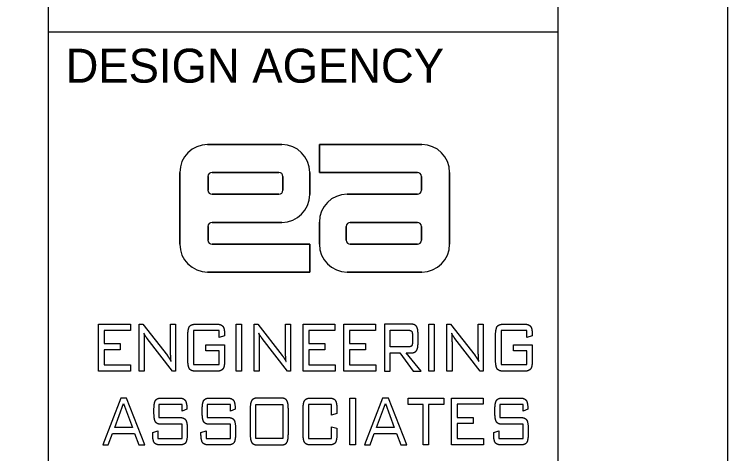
# Model space of a CAD drawing. Extents: x 0 to 34, y -1.9 to 22.
# Drawn here: x 31.899 to 34, y 3.757 to 5.052 of the extents above; entities that cross this region are included whole.
import ezdxf

# ---------------------------------------------------------------- set-up
doc = ezdxf.new("R2010")
doc.units = 0
for name, color, linetype in [('SH_Border', 7, 'Continuous'), ('SH_Cut_Line', 7, 'Continuous'), ('SH_Data', 7, 'Continuous'), ('TX_X_20', 7, 'Continuous')]:
    doc.layers.add(name, color=color, linetype=linetype)

msp = doc.modelspace()

# ---------------------------------------------------------------- linework, layer by layer
at = {"layer": 'SH_Border'}
for p, q in [((32, 0.5), (32, 21.5)), ((32, 5), (33.5, 5))]:
    msp.add_line(p, q, dxfattribs=at)
msp.add_lwpolyline([(1.5, 21.5), (33.5, 21.5), (33.5, 0.5), (1.5, 0.5)], close=True, dxfattribs=at)
at = {"layer": 'SH_Cut_Line'}
msp.add_lwpolyline([(0, 0), (34, 0), (34, 22), (0, 22)], close=True, dxfattribs=at)
at = {"layer": 'SH_Data'}
msp.add_line((32.75, 4), (32.75, 4), dxfattribs=at)
at = {"layer": 'TX_X_20'}
for p, q in [((32.6869, 4.6677), (32.4684, 4.6677)), ((32.4684, 4.6677), (32.6869, 4.6677)), ((32.7974, 4.6677), (33.0989, 4.6677)), ((32.7974, 4.5856), (32.7974, 4.6677)), ((32.3863, 4.5856), (32.3863, 4.3741)), ((32.3863, 4.3741), (32.3863, 4.5856)), ((32.4812, 4.5856), (32.678, 4.5856)), ((32.678, 4.5856), (32.4812, 4.5856)), ((32.7689, 4.5204), (32.7689, 4.5856)), ((32.7689, 4.5856), (32.7689, 4.5204)), ((33.086, 4.5856), (32.7974, 4.5856)), ((33.1809, 4.3741), (33.1809, 4.5856)), ((33.1809, 4.5856), (33.1809, 4.3741)), ((32.4694, 4.5332), (32.4694, 4.5738)), ((32.4694, 4.5738), (32.4694, 4.5332)), ((32.6898, 4.5738), (32.6898, 4.5332)), ((32.6898, 4.5332), (32.6898, 4.5738)), ((33.0979, 4.5738), (33.0979, 4.5332)), ((33.0979, 4.5332), (33.0979, 4.5738)), ((32.678, 4.5214), (32.4812, 4.5214)), ((32.4812, 4.5214), (32.678, 4.5214)), ((33.086, 4.5214), (32.8794, 4.5214)), ((32.8794, 4.5214), (33.086, 4.5214)), ((32.4812, 4.4383), (32.6869, 4.4383)), ((32.6869, 4.4383), (32.4812, 4.4383)), ((32.7974, 4.4393), (32.7974, 4.3741)), ((32.7974, 4.3741), (32.7974, 4.4393)), ((32.8883, 4.4383), (33.086, 4.4383)), ((33.086, 4.4383), (32.8883, 4.4383)), ((32.4694, 4.3859), (32.4694, 4.4265)), ((32.4694, 4.4265), (32.4694, 4.3859)), ((32.8765, 4.3859), (32.8765, 4.4265)), ((32.8765, 4.4265), (32.8765, 4.3859)), ((33.0979, 4.4265), (33.0979, 4.3859)), ((33.0979, 4.3859), (33.0979, 4.4265)), ((32.4812, 4.3741), (32.7689, 4.3741)), ((32.7689, 4.3741), (32.7689, 4.292)), ((33.086, 4.3741), (32.8883, 4.3741)), ((32.8883, 4.3741), (33.086, 4.3741)), ((32.7689, 4.292), (32.4684, 4.292)), ((32.8794, 4.292), (33.0989, 4.292)), ((33.0989, 4.292), (32.8794, 4.292)), ((32.4329, 4.1384), (32.4956, 4.1384)), ((33.339, 4.1384), (33.4017, 4.1384)), ((32.4101, 4.0328), (32.4101, 4.1057)), ((33.0715, 4.1062), (33.0715, 4.086)), ((33.0879, 4.0806), (33.0879, 4.1116)), ((33.3163, 4.0328), (33.3163, 4.1057)), ((32.4956, 4), (32.4329, 4)), ((33.4017, 4), (33.339, 4)), ((32.3328, 3.9209), (32.3843, 3.9209)), ((32.475, 3.9209), (32.5265, 3.9209)), ((32.6834, 3.9209), (32.6165, 3.9209)), ((32.7722, 3.9209), (32.8264, 3.9209)), ((33.3369, 3.9209), (33.3884, 3.9209)), ((32.3103, 3.8761), (32.3103, 3.8882)), ((32.4525, 3.8761), (32.4525, 3.8882)), ((32.5937, 3.8882), (32.5937, 3.8152)), ((32.706, 3.8152), (32.706, 3.8882)), ((32.7495, 3.8152), (32.7495, 3.8882)), ((33.3144, 3.8761), (33.3144, 3.8882)), ((32.4082, 3.8308), (32.4082, 3.8152)), ((32.5504, 3.8308), (32.5504, 3.8152)), ((33.4123, 3.8308), (33.4123, 3.8152)), ((32.3857, 3.7825), (32.3293, 3.7825)), ((32.5279, 3.7825), (32.4715, 3.7825)), ((32.6165, 3.7825), (32.6834, 3.7825)), ((32.8264, 3.7825), (32.7722, 3.7825)), ((33.3898, 3.7825), (33.3334, 3.7825))]:
    msp.add_line(p, q, dxfattribs=at)
for points in [[(33.0989, 4.6677), (32.7974, 4.6677), (32.7974, 4.5856), (33.086, 4.5856)], [(32.4684, 4.292), (32.7689, 4.292), (32.7689, 4.3741), (32.4812, 4.3741)], [(32.2819, 4.0816), (32.2819, 4), (32.2671, 4), (32.2671, 4.1384), (32.2773, 4.1384), (32.3497, 4.0458)], [(32.3593, 4.0625), (32.3593, 4.1384), (32.3741, 4.1384), (32.3741, 4), (32.365, 4), (32.2906, 4.0962)], [(32.5183, 4.1072), (32.5183, 4.1038), (32.5022, 4.0992), (32.5022, 4.1196), (32.4263, 4.1196), (32.4263, 4.0192), (32.5022, 4.0192), (32.5022, 4.0599), (32.463, 4.0599), (32.463, 4.0775), (32.5183, 4.0775), (32.5183, 4.0328)], [(32.6204, 4.0816), (32.6204, 4), (32.6056, 4), (32.6056, 4.1384), (32.6158, 4.1384), (32.6883, 4.0458)], [(32.6978, 4.0625), (32.6978, 4.1384), (32.7126, 4.1384), (32.7126, 4), (32.7035, 4), (32.6291, 4.0962)], [(33.0674, 4.1384), (32.9893, 4.1384), (32.9893, 4), (33.0056, 4), (33.0056, 4.0539), (33.034, 4.0539), (33.0734, 4), (33.0974, 4), (33.0532, 4.0539), (33.0674, 4.0539)], [(33.061, 4.0718), (33.0056, 4.0718), (33.0056, 4.1205), (33.061, 4.1205)], [(33.188, 4.0816), (33.188, 4), (33.1732, 4), (33.1732, 4.1384), (33.1834, 4.1384), (33.2559, 4.0458)], [(33.2654, 4.0625), (33.2654, 4.1384), (33.2802, 4.1384), (33.2802, 4), (33.2711, 4), (33.1967, 4.0962)], [(33.4244, 4.1072), (33.4244, 4.1038), (33.4083, 4.0992), (33.4083, 4.1196), (33.3324, 4.1196), (33.3324, 4.0192), (33.4083, 4.0192), (33.4083, 4.0599), (33.3691, 4.0599), (33.3691, 4.0775), (33.4244, 4.0775), (33.4244, 4.0328)], [(32.407, 3.8905), (32.407, 3.8877), (32.3932, 3.882), (32.3932, 3.9021), (32.3248, 3.9021), (32.3248, 3.8635), (32.3857, 3.8635)], [(32.5493, 3.8905), (32.5493, 3.8877), (32.5354, 3.882), (32.5354, 3.9021), (32.467, 3.9021), (32.467, 3.8635), (32.5279, 3.8635)], [(32.849, 3.8882), (32.849, 3.8751), (32.8327, 3.8708), (32.8327, 3.9021), (32.7656, 3.9021), (32.7656, 3.8018), (32.8327, 3.8018), (32.8327, 3.8364), (32.849, 3.8316), (32.849, 3.8152)], [(33.4112, 3.8905), (33.4112, 3.8877), (33.3973, 3.882), (33.3973, 3.9021), (33.3289, 3.9021), (33.3289, 3.8635), (33.3898, 3.8635)], [(32.3065, 3.8152), (32.3065, 3.819), (32.3215, 3.824), (32.3215, 3.8018), (32.3937, 3.8018), (32.3937, 3.8434), (32.3328, 3.8434)], [(32.4487, 3.8152), (32.4487, 3.819), (32.4637, 3.824), (32.4637, 3.8018), (32.5359, 3.8018), (32.5359, 3.8434), (32.475, 3.8434)], [(33.3107, 3.8152), (33.3107, 3.819), (33.3257, 3.824), (33.3257, 3.8018), (33.3978, 3.8018), (33.3978, 3.8434), (33.3369, 3.8434)]]:
    msp.add_lwpolyline(points, dxfattribs=at)
for points in [[(32.1474, 4), (32.1474, 4.1384), (32.2407, 4.1384), (32.2407, 4.1198), (32.1637, 4.1198), (32.1637, 4.0813), (32.2108, 4.0813), (32.2108, 4.0631), (32.1637, 4.0631), (32.1637, 4.019), (32.2414, 4.019), (32.2414, 4)], [(32.552, 4), (32.552, 4.1384), (32.5682, 4.1384), (32.5682, 4)], [(32.75, 4), (32.75, 4.1384), (32.8433, 4.1384), (32.8433, 4.1198), (32.7662, 4.1198), (32.7662, 4.0813), (32.8133, 4.0813), (32.8133, 4.0631), (32.7662, 4.0631), (32.7662, 4.019), (32.844, 4.019), (32.844, 4)], [(32.8697, 4), (32.8697, 4.1384), (32.9629, 4.1384), (32.9629, 4.1198), (32.8859, 4.1198), (32.8859, 4.0813), (32.933, 4.0813), (32.933, 4.0631), (32.8859, 4.0631), (32.8859, 4.019), (32.9637, 4.019), (32.9637, 4)], [(33.1196, 4), (33.1196, 4.1384), (33.1358, 4.1384), (33.1358, 4)], [(32.1595, 3.7825), (32.1755, 3.7825), (32.1879, 3.8166), (32.2534, 3.8166), (32.2658, 3.7825), (32.2836, 3.7825), (32.2297, 3.9209), (32.2124, 3.9209)], [(32.8873, 3.7825), (32.8873, 3.9209), (32.9036, 3.9209), (32.9036, 3.7825)], [(32.9305, 3.7825), (32.9465, 3.7825), (32.9589, 3.8166), (33.0244, 3.8166), (33.0368, 3.7825), (33.0546, 3.7825), (33.0008, 3.9209), (32.9834, 3.9209)], [(33.1192, 3.9021), (33.1192, 3.7825), (33.103, 3.7825), (33.103, 3.9021), (33.0588, 3.9021), (33.0588, 3.9209), (33.1636, 3.9209), (33.1636, 3.9021)], [(33.1866, 3.7825), (33.1866, 3.9209), (33.2798, 3.9209), (33.2798, 3.9024), (33.2028, 3.9024), (33.2028, 3.8639), (33.2499, 3.8639), (33.2499, 3.8456), (33.2028, 3.8456), (33.2028, 3.8015), (33.2806, 3.8015), (33.2806, 3.7825)], [(32.1946, 3.8342), (32.2207, 3.9051), (32.2468, 3.8342)], [(32.6099, 3.8018), (32.6099, 3.9021), (32.69, 3.9021), (32.69, 3.8018)], [(32.9657, 3.8342), (32.9917, 3.9051), (33.0178, 3.8342)]]:
    msp.add_lwpolyline(points, close=True, dxfattribs=at)
for centre, radius, start, end in [((32.4684, 4.5856), 0.0821, 90, 180), ((32.4684, 4.5856), 0.0821, 90, 180), ((32.6869, 4.5856), 0.0821, 0, 90), ((32.6869, 4.5856), 0.0821, 0, 90), ((33.0989, 4.5856), 0.0821, 0, 90), ((33.0989, 4.5856), 0.0821, 0, 90), ((32.4812, 4.5738), 0.0119, 90, 180), ((32.4812, 4.5738), 0.0119, 90, 180), ((32.678, 4.5738), 0.0119, 0, 90), ((32.678, 4.5738), 0.0119, 0, 90), ((33.086, 4.5738), 0.0119, 0, 90), ((33.086, 4.5738), 0.0119, 0, 90), ((32.4812, 4.5332), 0.0119, 180, 270), ((32.4812, 4.5332), 0.0119, 180, 270), ((32.678, 4.5332), 0.0119, 270, 0), ((32.678, 4.5332), 0.0119, 270, 0), ((32.6869, 4.5204), 0.0821, 270, 360), ((32.6869, 4.5204), 0.0821, 270, 360), ((32.8794, 4.4393), 0.0821, 90, 180), ((32.8794, 4.4393), 0.0821, 90, 180), ((33.086, 4.5332), 0.0119, 270, 0), ((33.086, 4.5332), 0.0119, 270, 0), ((32.4812, 4.4265), 0.0119, 90, 180), ((32.4812, 4.4265), 0.0119, 90, 180), ((32.8883, 4.4265), 0.0119, 90, 180), ((32.8883, 4.4265), 0.0119, 90, 180), ((33.086, 4.4265), 0.0119, 0, 90), ((33.086, 4.4265), 0.0119, 0, 90), ((32.4684, 4.3741), 0.0821, 180, 270), ((32.4684, 4.3741), 0.0821, 180, 270), ((32.4812, 4.3859), 0.0119, 180, 270), ((32.4812, 4.3859), 0.0119, 180, 270), ((32.8794, 4.3741), 0.0821, 180, 270), ((32.8794, 4.3741), 0.0821, 180, 270), ((32.8883, 4.3859), 0.0119, 180, 270), ((32.8883, 4.3859), 0.0119, 180, 270), ((33.086, 4.3859), 0.0119, 270, 0), ((33.086, 4.3859), 0.0119, 270, 0), ((33.0989, 4.3741), 0.0821, 270, 360), ((33.0989, 4.3741), 0.0821, 270, 360)]:
    msp.add_arc(centre, radius, start, end, dxfattribs=at)
for points in [[(32.4101, 4.1057), (32.4101, 4.1245), (32.4149, 4.1315)], [(32.4149, 4.1315), (32.4196, 4.1384), (32.4329, 4.1384)], [(32.4956, 4.1384), (32.5086, 4.1384), (32.5134, 4.1317)], [(32.5134, 4.1317), (32.5183, 4.1249), (32.5183, 4.1072)], [(33.061, 4.1205), (33.067, 4.1205), (33.0692, 4.1173)], [(33.0831, 4.1321), (33.0783, 4.1384), (33.0674, 4.1384)], [(33.0879, 4.1116), (33.0879, 4.1257), (33.0831, 4.1321)], [(33.3163, 4.1057), (33.3163, 4.1245), (33.321, 4.1315)], [(33.321, 4.1315), (33.3257, 4.1384), (33.339, 4.1384)], [(33.4017, 4.1384), (33.4147, 4.1384), (33.4196, 4.1317)], [(33.4196, 4.1317), (33.4244, 4.1249), (33.4244, 4.1072)], [(32.2889, 4.0983), (32.2834, 4.1054), (32.2808, 4.1118)], [(32.2808, 4.1118), (32.2813, 4.1055), (32.2816, 4.0984)], [(32.2816, 4.0984), (32.2819, 4.0913), (32.2819, 4.0816)], [(32.2906, 4.0962), (32.29, 4.0969), (32.2889, 4.0983)], [(32.6275, 4.0983), (32.622, 4.1054), (32.6193, 4.1118)], [(32.6193, 4.1118), (32.6199, 4.1055), (32.6201, 4.0984)], [(32.6201, 4.0984), (32.6204, 4.0913), (32.6204, 4.0816)], [(32.6291, 4.0962), (32.6286, 4.0969), (32.6275, 4.0983)], [(33.0692, 4.1173), (33.0715, 4.1141), (33.0715, 4.1062)], [(33.1951, 4.0983), (33.1896, 4.1054), (33.1869, 4.1118)], [(33.1869, 4.1118), (33.1875, 4.1055), (33.1877, 4.0984)], [(33.1877, 4.0984), (33.188, 4.0913), (33.188, 4.0816)], [(33.1967, 4.0962), (33.1962, 4.0969), (33.1951, 4.0983)], [(33.0715, 4.086), (33.0715, 4.0781), (33.0693, 4.0749)], [(33.0831, 4.0603), (33.0879, 4.0666), (33.0879, 4.0806)], [(32.3596, 4.0424), (32.3593, 4.0496), (32.3593, 4.0625)], [(32.6982, 4.0424), (32.6978, 4.0496), (32.6978, 4.0625)], [(33.0693, 4.0749), (33.0671, 4.0718), (33.061, 4.0718)], [(33.0674, 4.0539), (33.0783, 4.0539), (33.0831, 4.0603)], [(33.2658, 4.0424), (33.2654, 4.0496), (33.2654, 4.0625)], [(32.3497, 4.0458), (32.3522, 4.0427), (32.355, 4.0382)], [(32.355, 4.0382), (32.3578, 4.0338), (32.3607, 4.0284)], [(32.3607, 4.0284), (32.36, 4.0351), (32.3596, 4.0424)], [(32.6883, 4.0458), (32.6907, 4.0427), (32.6935, 4.0382)], [(32.6935, 4.0382), (32.6963, 4.0338), (32.6993, 4.0284)], [(32.6993, 4.0284), (32.6985, 4.0351), (32.6982, 4.0424)], [(33.2559, 4.0458), (33.2583, 4.0427), (33.2611, 4.0382)], [(33.2611, 4.0382), (33.2639, 4.0338), (33.2669, 4.0284)], [(33.2669, 4.0284), (33.2661, 4.0351), (33.2658, 4.0424)], [(32.4149, 4.0069), (32.4101, 4.0139), (32.4101, 4.0328)], [(32.5183, 4.0328), (32.5183, 4.0138), (32.5135, 4.0069)], [(33.321, 4.0069), (33.3163, 4.0139), (33.3163, 4.0328)], [(33.4244, 4.0328), (33.4244, 4.0138), (33.4197, 4.0069)], [(32.4329, 4), (32.4196, 4), (32.4149, 4.0069)], [(32.5135, 4.0069), (32.5088, 4), (32.4956, 4)], [(33.339, 4), (33.3257, 4), (33.321, 4.0069)], [(33.4197, 4.0069), (33.4149, 4), (33.4017, 4)], [(32.3103, 3.8882), (32.3103, 3.9072), (32.3149, 3.914)], [(32.3149, 3.914), (32.3196, 3.9209), (32.3328, 3.9209)], [(32.3843, 3.9209), (32.3972, 3.9209), (32.4021, 3.9142)], [(32.4021, 3.9142), (32.407, 3.9074), (32.407, 3.8905)], [(32.4525, 3.8882), (32.4525, 3.9072), (32.4571, 3.914)], [(32.4571, 3.914), (32.4618, 3.9209), (32.475, 3.9209)], [(32.5265, 3.9209), (32.5394, 3.9209), (32.5443, 3.9142)], [(32.5443, 3.9142), (32.5493, 3.9074), (32.5493, 3.8905)], [(32.5984, 3.914), (32.5937, 3.907), (32.5937, 3.8882)], [(32.6165, 3.9209), (32.6032, 3.9209), (32.5984, 3.914)], [(32.7013, 3.914), (32.6965, 3.9209), (32.6834, 3.9209)], [(32.706, 3.8882), (32.706, 3.9072), (32.7013, 3.914)], [(32.7495, 3.8882), (32.7495, 3.9072), (32.7543, 3.914)], [(32.7543, 3.914), (32.759, 3.9209), (32.7722, 3.9209)], [(32.8264, 3.9209), (32.8396, 3.9209), (32.8443, 3.9141)], [(32.8443, 3.9141), (32.849, 3.9073), (32.849, 3.8882)], [(33.3144, 3.8882), (33.3144, 3.9072), (33.3191, 3.914)], [(33.3191, 3.914), (33.3237, 3.9209), (33.3369, 3.9209)], [(33.3884, 3.9209), (33.4014, 3.9209), (33.4063, 3.9142)], [(33.4063, 3.9142), (33.4112, 3.9074), (33.4112, 3.8905)], [(32.3149, 3.8503), (32.3103, 3.8571), (32.3103, 3.8761)], [(32.4571, 3.8503), (32.4525, 3.8571), (32.4525, 3.8761)], [(33.3191, 3.8503), (33.3144, 3.8571), (33.3144, 3.8761)], [(32.3328, 3.8434), (32.3196, 3.8434), (32.3149, 3.8503)], [(32.3857, 3.8635), (32.3986, 3.8635), (32.4034, 3.8566)], [(32.4034, 3.8566), (32.4082, 3.8498), (32.4082, 3.8308)], [(32.475, 3.8434), (32.4618, 3.8434), (32.4571, 3.8503)], [(32.5279, 3.8635), (32.5408, 3.8635), (32.5456, 3.8566)], [(32.5456, 3.8566), (32.5504, 3.8498), (32.5504, 3.8308)], [(33.3369, 3.8434), (33.3237, 3.8434), (33.3191, 3.8503)], [(33.3898, 3.8635), (33.4028, 3.8635), (33.4075, 3.8566)], [(33.4075, 3.8566), (33.4123, 3.8498), (33.4123, 3.8308)], [(32.3113, 3.7894), (32.3065, 3.7963), (32.3065, 3.8152)], [(32.4082, 3.8152), (32.4082, 3.7961), (32.4035, 3.7893)], [(32.4535, 3.7894), (32.4487, 3.7963), (32.4487, 3.8152)], [(32.5504, 3.8152), (32.5504, 3.7961), (32.5457, 3.7893)], [(32.5937, 3.8152), (32.5937, 3.7964), (32.5984, 3.7895)], [(32.7013, 3.7893), (32.706, 3.7961), (32.706, 3.8152)], [(32.7543, 3.7894), (32.7495, 3.7963), (32.7495, 3.8152)], [(32.849, 3.8152), (32.849, 3.7961), (32.8443, 3.7893)], [(33.3154, 3.7894), (33.3107, 3.7963), (33.3107, 3.8152)], [(33.4123, 3.8152), (33.4123, 3.7961), (33.4076, 3.7893)], [(32.3293, 3.7825), (32.3161, 3.7825), (32.3113, 3.7894)], [(32.4035, 3.7893), (32.3988, 3.7825), (32.3857, 3.7825)], [(32.4715, 3.7825), (32.4583, 3.7825), (32.4535, 3.7894)], [(32.5457, 3.7893), (32.541, 3.7825), (32.5279, 3.7825)], [(32.5984, 3.7895), (32.6032, 3.7825), (32.6165, 3.7825)], [(32.6834, 3.7825), (32.6965, 3.7825), (32.7013, 3.7893)], [(32.7722, 3.7825), (32.759, 3.7825), (32.7543, 3.7894)], [(32.8443, 3.7893), (32.8396, 3.7825), (32.8264, 3.7825)], [(33.3334, 3.7825), (33.3202, 3.7825), (33.3154, 3.7894)], [(33.4076, 3.7893), (33.4029, 3.7825), (33.3898, 3.7825)]]:
    msp.add_open_spline(points, degree=2, dxfattribs=at)

# ---------------------------------------------------------------- texts
at = {"layer": 'SH_Data'}
msp.add_text('DESIGN AGENCY', height=0.1, dxfattribs=at).set_placement((32.05, 4.85))

doc.saveas('drawing.dxf')
